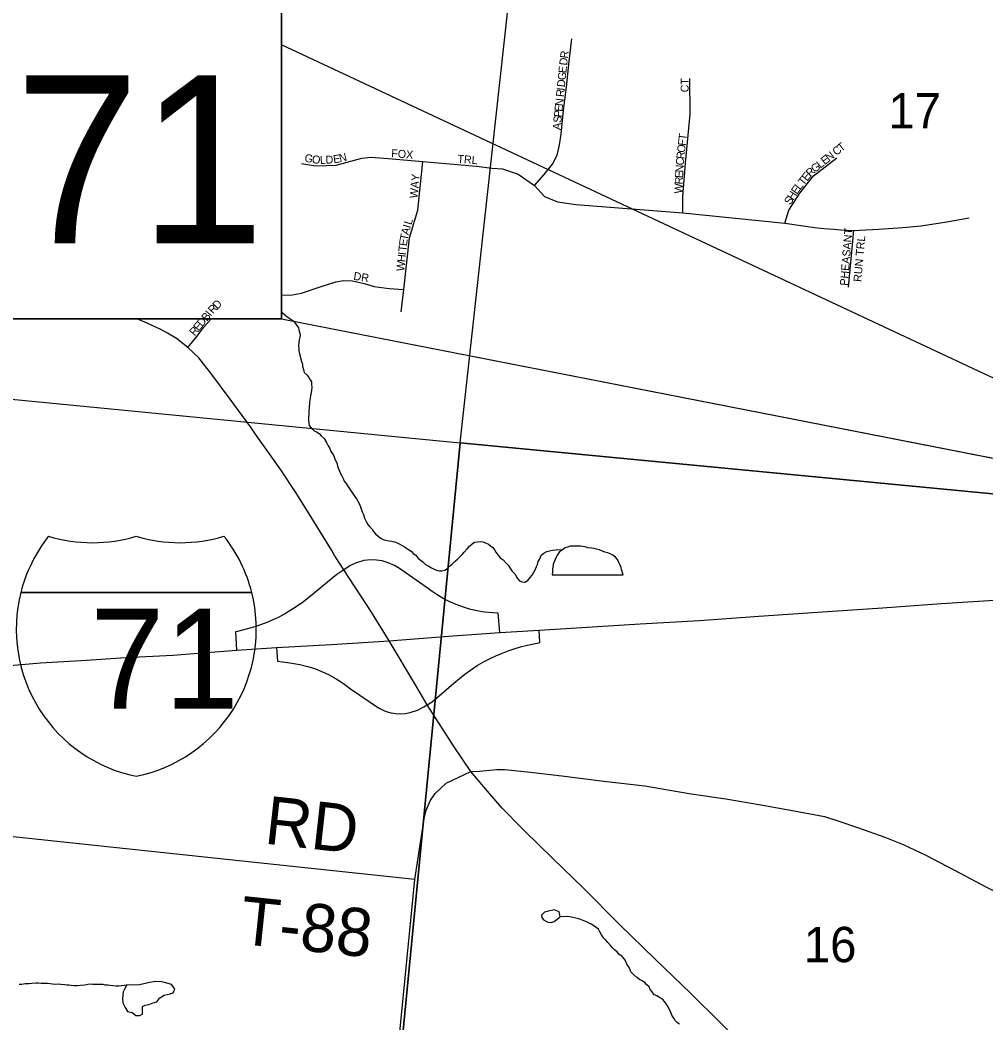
# Model space of a CAD drawing. Extents: x 0 to 34, y -4 to 22.
# Drawn here: x 7.607 to 8.412, y 19.435 to 20.27 of the extents above; entities that cross this region are included whole.
import ezdxf

# ---------------------------------------------------------------- set-up
doc = ezdxf.new("R2010")
doc.units = 0
for name, color, linetype in [('GM_X_Interchange_Ramps', 7, 'Continuous'), ('GM_X_Interstate_Route', 7, 'Continuous'), ('GM_X_Interstate_Shield', 7, 'Continuous'), ('GM_X_Minor_Lake', 7, 'Continuous'), ('GM_X_Minor_River', 7, 'Continuous'), ('GM_X_Section', 7, 'Continuous'), ('GM_X_Section_Text', 7, 'Continuous'), ('GM_X_State_Route', 7, 'Continuous'), ('GM_X_Township_Road', 7, 'Continuous'), ('GM_X_Township_Road_Text', 7, 'Continuous'), ('GM_X_Township_Subdivision', 7, 'Continuous'), ('GM_X_Township_Subdivision_Text', 7, 'Continuous'), ('SH_Text', 7, 'Continuous'), ('TX_P_100', 7, 'Continuous')]:
    doc.layers.add(name, color=color, linetype=linetype)

msp = doc.modelspace()

# ---------------------------------------------------------------- linework, layer by layer
at = {"layer": 'GM_X_Interchange_Ramps'}
for points in [[(8.00687, 19.76006), (8.00574, 19.77625), (8.00129, 19.77646), (7.9942, 19.77717), (7.98772, 19.77826), (7.9818, 19.77966), (7.9775, 19.78092), (7.97058, 19.78341), (7.96544, 19.78564), (7.95981, 19.78851), (7.95477, 19.79147), (7.9506, 19.79424), (7.94843, 19.7958), (7.92328, 19.8133), (7.9192, 19.81582), (7.9141, 19.81813), (7.90899, 19.81966), (7.90419, 19.82046), (7.8994, 19.82067), (7.89365, 19.81996), (7.88674, 19.81794), (7.88272, 19.81586), (7.87708, 19.81227)], [(7.87708, 19.81227), (7.87109, 19.80844), (7.84928, 19.79033), (7.84334, 19.78563), (7.83738, 19.78143), (7.83292, 19.77859), (7.82758, 19.77549), (7.8217, 19.77245), (7.81723, 19.77036), (7.81278, 19.76848), (7.8075, 19.76648), (7.80368, 19.76519), (7.79672, 19.76316), (7.78838, 19.76085), (7.78672, 19.76063), (7.78774, 19.74538)], [(7.94653, 19.69988), (7.95053, 19.70239), (7.96869, 19.718), (7.97327, 19.7219), (7.97792, 19.72553), (7.98254, 19.72883), (7.9882, 19.7325), (7.99401, 19.73589), (7.99883, 19.73842), (8.00365, 19.74072), (8.00833, 19.74274), (8.01387, 19.74487), (8.01905, 19.74662), (8.02517, 19.74841), (8.03246, 19.75015), (8.03947, 19.7516), (8.04038, 19.75172), (8.03973, 19.76212)], [(7.82101, 19.74755), (7.82177, 19.73624), (7.83198, 19.73481), (7.84026, 19.73348), (7.84712, 19.73179), (7.85345, 19.72973), (7.86417, 19.72518), (7.87054, 19.72162), (7.87665, 19.7177), (7.88268, 19.7133), (7.90596, 19.69734), (7.91156, 19.69451), (7.91612, 19.69309), (7.92257, 19.69226), (7.92803, 19.69256), (7.93223, 19.69342), (7.93842, 19.69528), (7.94378, 19.69817), (7.94653, 19.69988)]]:
    msp.add_lwpolyline(points, dxfattribs=at)
at = {"layer": 'GM_X_Interstate_Route'}
msp.add_lwpolyline([(7.59904, 19.73266), (7.62426, 19.73475), (7.65806, 19.7369), (7.69534, 19.73924), (7.73449, 19.74128), (7.78774, 19.74538), (7.82101, 19.74755), (7.86674, 19.75024), (7.91493, 19.7531), (7.96412, 19.75706), (8.00687, 19.76006), (8.01643, 19.76066), (8.03973, 19.76212), (8.12398, 19.76725), (8.17333, 19.77012), (8.2227, 19.77378), (8.27152, 19.77693), (8.32168, 19.7803), (8.32195, 19.7803), (8.37507, 19.78414), (8.44078, 19.7885)], dxfattribs=at)
at = {"layer": 'GM_X_Interstate_Shield'}
for p, q in [((7.60795, 19.79348), (7.80032, 19.79348)), ((7.80032, 19.79348), (7.60795, 19.79348)), ((7.80032, 19.79348), (7.60795, 19.79348))]:
    msp.add_line(p, q, dxfattribs=at)
for centre, start, end in [((7.72913, 19.76283), 141.66896, 165.80665), ((7.66761, 19.95991), 253.00908, 286.99093), ((7.74066, 19.95991), 253.00908, 286.99093), ((7.67913, 19.76283), 14.19335, 38.33104), ((7.72913, 19.76283), 165.80665, 258.46304), ((7.67913, 19.76283), 281.53696, 14.19335)]:
    msp.add_arc(centre, 0.125, start, end, dxfattribs=at)
at = {"layer": 'GM_X_Minor_Lake'}
for points in [[(8.10968, 19.80819), (8.10848, 19.8125), (8.10801, 19.81438), (8.10726, 19.81628), (8.10627, 19.81844), (8.10501, 19.82089), (8.10346, 19.82281), (8.10111, 19.82448), (8.099, 19.82562), (8.09689, 19.82648), (8.09449, 19.82709), (8.09265, 19.82795), (8.09, 19.82883), (8.08761, 19.82944), (8.08548, 19.83004), (8.08335, 19.83037), (8.08068, 19.83072), (8.07882, 19.83105), (8.07616, 19.83166), (8.07429, 19.83199), (8.07242, 19.83205), (8.07028, 19.83211), (8.0684, 19.8319), (8.06572, 19.83198), (8.06329, 19.83126), (8.06139, 19.83052), (8.05919, 19.82898), (8.05672, 19.82719), (8.05476, 19.82458), (8.0539, 19.82273), (8.05303, 19.82089), (8.05217, 19.81905), (8.05155, 19.81666), (8.05122, 19.8148), (8.05089, 19.81294), (8.05081, 19.81054), (8.05073, 19.80814)], [(8.05073, 19.80814), (8.1078, 19.80825), (8.10968, 19.80819)], [(7.69633, 19.46653), (7.69437, 19.46309), (7.69324, 19.46071), (7.69258, 19.45564), (7.69302, 19.45162), (7.6948, 19.44783), (7.69686, 19.44457), (7.70059, 19.44367), (7.70374, 19.44119), (7.70669, 19.44112), (7.70939, 19.44212), (7.70922, 19.44587), (7.70928, 19.44855), (7.71146, 19.44984), (7.71468, 19.45029), (7.71739, 19.4513), (7.72117, 19.45254), (7.72366, 19.4557), (7.72746, 19.45801), (7.73231, 19.45923), (7.73474, 19.45998), (7.73617, 19.46342), (7.73358, 19.46696), (7.72879, 19.46842), (7.72505, 19.46904), (7.71997, 19.46943), (7.71405, 19.46824)], [(7.71405, 19.46824), (7.70678, 19.46654), (7.70061, 19.46642), (7.69633, 19.46653)]]:
    msp.add_lwpolyline(points, dxfattribs=at)
at = {"layer": 'GM_X_Minor_River'}
for points in [[(7.8251, 20.02729), (7.82593, 20.02641), (7.82775, 20.02475), (7.83062, 20.02252), (7.83299, 20.02111), (7.83534, 20.01944), (7.83764, 20.01616), (7.83918, 20.01398), (7.83965, 20.01209), (7.84013, 20.01021), (7.8406, 20.00832), (7.84026, 20.0062)], [(7.84026, 20.0062), (7.83991, 20.0038), (7.83957, 20.00141), (7.83922, 19.99901), (7.83941, 19.9966), (7.83961, 19.99473), (7.84007, 19.99231), (7.84054, 19.99016), (7.84126, 19.98773), (7.84173, 19.98584), (7.84247, 19.98368), (7.84266, 19.98154), (7.84339, 19.97912), (7.84411, 19.97669), (7.84645, 19.97448), (7.84799, 19.97256), (7.849, 19.97066), (7.85001, 19.96876), (7.85022, 19.96688), (7.8504, 19.9642), (7.85005, 19.96181), (7.84972, 19.95995), (7.84937, 19.95729), (7.84903, 19.95516), (7.84839, 19.95198), (7.84823, 19.94717), (7.84789, 19.94505), (7.84777, 19.94131), (7.84771, 19.93944), (7.84763, 19.93704), (7.84781, 19.93436), (7.84828, 19.93248), (7.84982, 19.93056), (7.85242, 19.92807), (7.85427, 19.92722), (7.85636, 19.92582), (7.85818, 19.92389), (7.86051, 19.92168), (7.86255, 19.91841), (7.86407, 19.91569), (7.86508, 19.91379), (7.86632, 19.91081), (7.86811, 19.90835), (7.86885, 19.90646), (7.86959, 19.90457), (7.87059, 19.9024), (7.87134, 19.90051), (7.87181, 19.89862), (7.87279, 19.89592), (7.87404, 19.89321), (7.87504, 19.89104), (7.87656, 19.88832), (7.87729, 19.88616), (7.87884, 19.88425), (7.88062, 19.88152), (7.8819, 19.87961), (7.88317, 19.8777), (7.8847, 19.87525), (7.88625, 19.87333), (7.88752, 19.87142), (7.8888, 19.86951), (7.88981, 19.86761), (7.89078, 19.86464), (7.89226, 19.86059), (7.89352, 19.85841), (7.89423, 19.85545), (7.89574, 19.85246), (7.897, 19.85002), (7.89881, 19.8481), (7.90062, 19.84617), (7.90163, 19.84427), (7.90344, 19.84234), (7.90552, 19.84041), (7.90735, 19.83902), (7.90971, 19.83761), (7.91211, 19.837), (7.9145, 19.83639), (7.9169, 19.83605), (7.9193, 19.83571), (7.92141, 19.83484), (7.92379, 19.8337), (7.92562, 19.83257), (7.92746, 19.83145), (7.93087, 19.82921), (7.93324, 19.8278), (7.93478, 19.82588), (7.93688, 19.82448), (7.93868, 19.82229), (7.94103, 19.82034), (7.94286, 19.81895), (7.94519, 19.81674), (7.94783, 19.81532), (7.95019, 19.81392), (7.9523, 19.81278), (7.95414, 19.81192), (7.95654, 19.81158), (7.95869, 19.81152), (7.96111, 19.81198), (7.96331, 19.81351), (7.96497, 19.81533), (7.96718, 19.81713)], [(7.96718, 19.81713), (7.96966, 19.81946), (7.9716, 19.82127), (7.97353, 19.82281), (7.97548, 19.82516), (7.97715, 19.82697), (7.97965, 19.82984), (7.98159, 19.83191), (7.98407, 19.83397), (7.98599, 19.83525), (7.98842, 19.83571), (7.99084, 19.8359), (7.99297, 19.83557), (7.99508, 19.8347), (7.99746, 19.83356), (7.99929, 19.83217), (8.00112, 19.83078), (8.00266, 19.82886), (8.00367, 19.82696), (8.0052, 19.82477), (8.00727, 19.8223), (8.00989, 19.82062), (8.01221, 19.81788), (8.01403, 19.81622), (8.0153, 19.81404), (8.01709, 19.81158), (8.01941, 19.80884), (8.02069, 19.80693), (8.0217, 19.80503), (8.02351, 19.8031), (8.02536, 19.80224), (8.02776, 19.8019), (8.03049, 19.80369), (8.03189, 19.80551), (8.03385, 19.80786), (8.03527, 19.81022), (8.03669, 19.81285), (8.03757, 19.81496), (8.03843, 19.8168), (8.03904, 19.81918), (8.03991, 19.82103), (8.04077, 19.82287), (8.04164, 19.82472), (8.04356, 19.82626), (8.04602, 19.82752), (8.04845, 19.82824), (8.05088, 19.8287), (8.0533, 19.8289), (8.05545, 19.8291), (8.05919, 19.82898)], [(8.05729, 19.52325), (8.05633, 19.52755), (8.05235, 19.52925), (8.0475, 19.52803), (8.04426, 19.52704), (8.04179, 19.5247), (8.04202, 19.52282), (8.04331, 19.52091)], [(8.04331, 19.52091), (8.04701, 19.51895), (8.04968, 19.51862), (8.05238, 19.51936), (8.05729, 19.52325)], [(8.15679, 19.4338), (8.15495, 19.43492), (8.15314, 19.43685), (8.15186, 19.43876), (8.15035, 19.44147), (8.1491, 19.44445), (8.14785, 19.44689), (8.14684, 19.4488), (8.14556, 19.45071), (8.14455, 19.45261), (8.14248, 19.45481), (8.14011, 19.45622), (8.13774, 19.45736), (8.13563, 19.45822), (8.13384, 19.46095), (8.1323, 19.46287), (8.1313, 19.46504), (8.12948, 19.4667), (8.12767, 19.46862), (8.12557, 19.47002), (8.12346, 19.47116), (8.12111, 19.47283), (8.1185, 19.47505), (8.11617, 19.47752), (8.11518, 19.47996), (8.11417, 19.48186), (8.1129, 19.48377), (8.1119, 19.48621), (8.11089, 19.48811), (8.10882, 19.49031), (8.10621, 19.49226), (8.10467, 19.49418), (8.10258, 19.49584), (8.10076, 19.4975), (8.09921, 19.49942), (8.09688, 19.5019), (8.09534, 19.50382), (8.09352, 19.50547), (8.09173, 19.5082), (8.09022, 19.51092), (8.08922, 19.51309), (8.08739, 19.51448), (8.08529, 19.51588), (8.08319, 19.51728), (8.08135, 19.51814), (8.07923, 19.51901), (8.07685, 19.51988), (8.07447, 19.52102), (8.07262, 19.52161), (8.07023, 19.52222), (8.06784, 19.52283), (8.06544, 19.52317), (8.06357, 19.5235), (8.05729, 19.52325)], [(7.60653, 19.46709), (7.60868, 19.46729), (7.61164, 19.46773), (7.61486, 19.4679), (7.61701, 19.4681), (7.62077, 19.46825), (7.62264, 19.46819), (7.62478, 19.46813), (7.62692, 19.46806), (7.63014, 19.46796), (7.63228, 19.4679), (7.63441, 19.46756), (7.63681, 19.46722), (7.63923, 19.46741), (7.64136, 19.46708), (7.6443, 19.46699), (7.64617, 19.46666), (7.64804, 19.46661), (7.64991, 19.46628), (7.65231, 19.46621), (7.65499, 19.46612), (7.65768, 19.46631), (7.66117, 19.46674), (7.66387, 19.46719), (7.66602, 19.46739), (7.66789, 19.46733), (7.66976, 19.46727), (7.67191, 19.4672), (7.67405, 19.46714), (7.67619, 19.46707)], [(7.67619, 19.46707), (7.67805, 19.46675), (7.68046, 19.46667), (7.68233, 19.46635), (7.68446, 19.46602), (7.68713, 19.46593), (7.68954, 19.46586), (7.69633, 19.46653)]]:
    msp.add_lwpolyline(points, dxfattribs=at)
at = {"layer": 'GM_X_Section'}
for points in [[(7.2896, 20.0213), (7.28612, 19.985), (7.97405, 19.91801), (8.0438, 20.5539), (7.34774, 20.62772), (7.33339, 20.47803), (7.8251, 20.47803), (7.8251, 20.0213)], [(8.0438, 20.5539), (8.73019, 20.4912), (8.66411, 19.85205), (7.97405, 19.91801)], [(7.28612, 19.985), (7.97405, 19.91801), (7.90105, 19.1654), (7.21731, 19.22831)], [(7.97405, 19.91801), (8.66411, 19.85205), (8.59171, 19.1029), (7.90105, 19.1654)]]:
    msp.add_lwpolyline(points, close=True, dxfattribs=at)
at = {"layer": 'GM_X_State_Route'}
for points in [[(7.80601, 19.92171), (7.80593, 19.92182), (7.79935, 19.93127), (7.78245, 19.95441), (7.76703, 19.97509), (7.75625, 19.98885), (7.74713, 19.99755), (7.7375, 20.00491), (7.73015, 20.0093), (7.72464, 20.01243), (7.7113, 20.01851), (7.70463, 20.0213)], [(7.86964, 19.82382), (7.86704, 19.82839), (7.85042, 19.85539), (7.83698, 19.87667), (7.82442, 19.89549), (7.81358, 19.91078), (7.80601, 19.92171)], [(7.98291, 19.64429), (7.96852, 19.6658), (7.94653, 19.69988), (7.93666, 19.71654), (7.91493, 19.7531), (7.90016, 19.77712), (7.87708, 19.81227), (7.86984, 19.82347), (7.86964, 19.82382)], [(7.98291, 19.64429), (7.99015, 19.64466), (8.00456, 19.64605), (8.01088, 19.64598), (8.03003, 19.64412), (8.05876, 19.6406), (8.09361, 19.63634), (8.12792, 19.63235), (8.14859, 19.62867), (8.16647, 19.62585), (8.1953, 19.6217), (8.22437, 19.61648), (8.25211, 19.61155), (8.27745, 19.60695), (8.28861, 19.60322), (8.30589, 19.59746), (8.32766, 19.58973), (8.34305, 19.5835), (8.36186, 19.57477), (8.39096, 19.55938), (8.41133, 19.54848), (8.43806, 19.53501)], [(8.02554, 19.59688), (8.02533, 19.59709), (8.00897, 19.61373), (7.99665, 19.62783), (7.98291, 19.64429)], [(8.21736, 19.40856), (8.19096, 19.43512), (8.16616, 19.45939), (8.13653, 19.48805), (8.10677, 19.51697), (8.07652, 19.54744), (8.05112, 19.57183), (8.02781, 19.59457), (8.02554, 19.59688)]]:
    msp.add_lwpolyline(points, dxfattribs=at)
at = {"layer": 'GM_X_Township_Road'}
for points in [[(7.9429, 19.59781), (7.94398, 19.60495), (7.94558, 19.612), (7.9489, 19.61998), (7.95316, 19.62597), (7.96227, 19.63452), (7.98291, 19.64429)], [(7.93631, 19.55446), (7.35562, 19.61598), (7.35117, 19.61747), (7.34941, 19.62082), (7.35001, 19.62425), (7.3528, 19.62451), (7.35519, 19.62254), (7.35658, 19.61901), (7.35562, 19.61611)], [(7.89749, 19.16191), (7.89749, 19.16191), (7.93631, 19.55446), (7.9429, 19.59781)]]:
    msp.add_lwpolyline(points, dxfattribs=at)
at = {"layer": 'GM_X_Township_Subdivision'}
for points in [[(8.03586, 20.13242), (8.04402, 20.14147), (8.05078, 20.15014), (8.05486, 20.15766), (8.05664, 20.16633), (8.05817, 20.17525), (8.05983, 20.19208), (8.06047, 20.19961), (8.06264, 20.2144), (8.06467, 20.23607), (8.0671, 20.25455)], [(8.1594, 20.10966), (8.1594, 20.12336), (8.16157, 20.15091), (8.16552, 20.19183), (8.16527, 20.22141)], [(7.84188, 20.15061), (7.85339, 20.14889), (7.87061, 20.14938), (7.89205, 20.15511), (7.89944, 20.156), (7.91388, 20.15479), (7.9429, 20.15233), (7.98767, 20.14861), (8.00029, 20.14695), (8.00909, 20.14631), (8.02235, 20.14172), (8.03586, 20.13242), (8.04428, 20.12311), (8.05511, 20.1189), (8.07041, 20.11648), (8.1594, 20.10966), (8.24442, 20.10095), (8.26916, 20.0973), (8.27702, 20.09652), (8.2855, 20.09606), (8.2912, 20.0956), (8.30184, 20.09483), (8.30662, 20.09529), (8.32281, 20.09606), (8.3427, 20.0973), (8.35782, 20.09884), (8.37771, 20.10177), (8.39806, 20.10547)], [(7.92481, 20.0273), (7.92692, 20.04572), (7.9317, 20.08869), (7.93875, 20.11186), (7.9429, 20.15233)], [(8.24442, 20.10095), (8.24768, 20.11175), (8.25683, 20.12594), (8.26818, 20.14045), (8.28773, 20.15558)], [(8.29759, 20.04783), (8.30184, 20.09483)], [(7.8251, 20.04121), (7.83257, 20.04101), (7.84175, 20.0426), (7.85813, 20.04833), (7.87044, 20.0521), (7.87681, 20.05325), (7.88427, 20.05293), (7.89403, 20.0507), (7.90225, 20.0484), (7.91481, 20.04655), (7.92692, 20.04572)], [(7.74713, 19.99755), (7.75474, 20.00684), (7.76022, 20.01423), (7.76648, 20.0213)]]:
    msp.add_lwpolyline(points, dxfattribs=at)
at = {"layer": 'SH_Text'}
msp.add_line((7.8251, 20.0213), (8.66314, 19.85741), dxfattribs=at)
msp.add_lwpolyline([(5.54309, 20.47803), (5.54309, 20.0213), (7.8251, 20.0213), (7.8251, 20.47803)], close=True, dxfattribs=at)
at = {"layer": 'TX_P_100'}
msp.add_lwpolyline([(7.8251, 20.0213), (8.66314, 19.85741), (7.8251, 20.24966)], close=True, dxfattribs=at)

# ---------------------------------------------------------------- texts
at = {"layer": 'GM_X_Interstate_Shield'}
msp.add_text('71', height=0.083333, dxfattribs=at).set_placement((7.66564, 19.69661))
at = {"layer": 'GM_X_Section_Text'}
for s, p in [('17', (8.33069, 20.17989)), ('16', (8.26029, 19.4855))]:
    msp.add_text(s, height=0.029444, rotation=0.00001, dxfattribs=at).set_placement(p)
at = {"layer": 'GM_X_Township_Road_Text'}
for s, rotation, p in [('RD', 353.60543, (7.81002, 19.58439)), ('T-88', 353.97305, (7.78924, 19.50089))]:
    msp.add_text(s, height=0.04, rotation=rotation, dxfattribs=at).set_placement(p)
at = {"layer": 'GM_X_Township_Subdivision_Text'}
for s, height, rotation, p in [('R', 0.00667, 82.52251, (8.06367, 20.23794)), ('E', 0.00667, 84.17304, (8.06236, 20.22574)), ('D', 0.00667, 83.51741, (8.06301, 20.23214)), ('G', 0.00667, 84.15457, (8.06176, 20.2199)), ('D', 0.00667, 84.18042, (8.06117, 20.21407)), ('CT', 0.006667, 90, (8.16429, 20.20998)), ('R', 0.00667, 84.18549, (8.06033, 20.20589)), ('I', 0.00667, 84.13283, (8.06087, 20.21114)), ('E', 0.00667, 84.15846, (8.05908, 20.19363)), ('N', 0.00667, 84.15457, (8.05955, 20.1983)), ('S', 0.00667, 84.15846, (8.05812, 20.1843)), ('P', 0.00667, 84.16977, (8.0586, 20.18897)), ('A', 0.00667, 84.17632, (8.05753, 20.17847)), ('T', 0.00667, 83.37315, (8.1624, 20.16988)), ('O', 0.00667, 83.36293, (8.16118, 20.15939)), ('F', 0.00667, 83.37315, (8.16186, 20.16522)), ('C', 0.00667, 38.40024, (8.28733, 20.15692)), ('T', 0.00667, 38.39961, (8.29147, 20.1602)), ('G', 0.00667, 347.10369, (7.84377, 20.15254)), ('O', 0.00667, 352.97163, (7.85022, 20.1511)), ('L', 0.00667, 2.40337, (7.85724, 20.15033)), ('D', 0.00667, 2.27401, (7.86192, 20.15053)), ('E', 0.00667, 9.1789, (7.86866, 20.15085)), ('N', 0.00667, 13.95488, (7.87389, 20.15172)), ('FOX', 0.006667, 355.48827, (7.91631, 20.15609)), ('TRL', 0.006667, 355.60387, (7.97146, 20.15139)), ('R', 0.00667, 83.47743, (8.16058, 20.15415)), ('E', 0.00667, 38.37819, (8.27767, 20.14927)), ('N', 0.00667, 38.40198, (8.28135, 20.15218)), ('N', 0.00667, 87.2009, (8.15984, 20.14314)), ('C', 0.00667, 84.91769, (8.16012, 20.14893)), ('G', 0.00667, 38.69735, (8.26942, 20.14269)), ('L', 0.00667, 38.41658, (8.274, 20.14635)), ('WAY', 0.006667, 84.80138, (7.93843, 20.12151)), ('R', 0.00667, 87.30371, (8.15937, 20.13318)), ('E', 0.00667, 87.29447, (8.15962, 20.13846)), ('T', 0.00667, 51.40846, (8.26008, 20.13192)), ('E', 0.00667, 51.40846, (8.26301, 20.13559)), ('R', 0.00667, 44.5878, (8.2658, 20.1391)), ('W', 0.00667, 87.30887, (8.15901, 20.12556)), ('E', 0.00667, 55.05946, (8.25457, 20.12447)), ('L', 0.00667, 52.01001, (8.25721, 20.12824)), ('S', 0.00667, 57.62101, (8.24896, 20.11561)), ('H', 0.00667, 57.64678, (8.25148, 20.11958)), ('I', 0.00667, 73.49701, (7.93247, 20.09634)), ('L', 0.00667, 73.49701, (7.9333, 20.09916)), ('T', 0.00667, 78.77671, (7.9301, 20.08622)), ('A', 0.00667, 75.25691, (7.93099, 20.09072)), ('PHEASANT', 0.006667, 85.30078, (8.29688, 20.04876)), ('RUN TRL', 0.006667, 85.15481, (8.30819, 20.05191)), ('T', 0.00667, 84.05641, (7.92901, 20.07707)), ('E', 0.00667, 82.29651, (7.92949, 20.08168)), ('H', 0.00667, 84.05641, (7.9281, 20.06832)), ('I', 0.00667, 84.05641, (7.9287, 20.07415)), ('W', 0.00667, 84.05641, (7.92731, 20.06073)), ('DR', 0.006667, 351.02147, (7.88472, 20.05392)), ('R', 0.00667, 46.2364, (7.76795, 20.02506)), ('D', 0.00667, 45.15451, (7.77158, 20.02885)), ('D', 0.00667, 50.65677, (7.75911, 20.01427)), ('B', 0.00667, 50.68558, (7.76284, 20.01881)), ('I', 0.00667, 50.69296, (7.76618, 20.02289)), ('R', 0.00667, 50.67641, (7.7528, 20.00656)), ('E', 0.00667, 50.67022, (7.75614, 20.01064))]:
    msp.add_text(s, height=height, rotation=rotation, dxfattribs=at).set_placement(p)
at = {"layer": 'SH_Text'}
msp.add_text('WAR-71-1371', height=0.14, dxfattribs=at).set_placement((6.62492, 20.08422))

doc.saveas('drawing.dxf')
